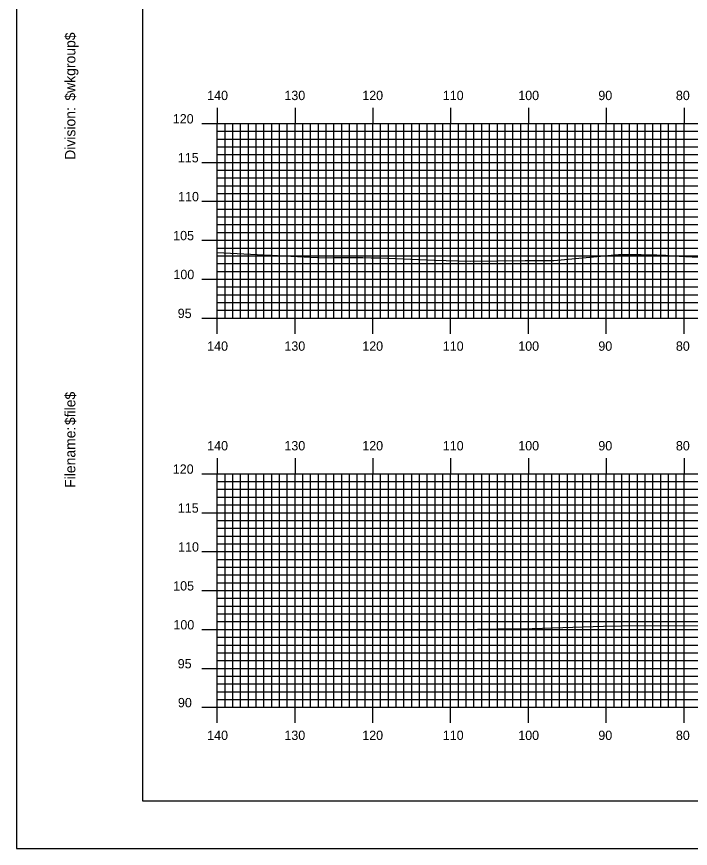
# Model space of a CAD drawing. Extents: x 1765726 to 1766069, y 442591 to 442811.
# Drawn here: x 1765726.1 to 1765812.7, y 442590.5 to 442697.4 of the extents above; entities that cross this region are included whole.
import ezdxf

# ---------------------------------------------------------------- set-up
doc = ezdxf.new("R2010")
doc.units = 0
for name, color, linetype in [('BORDER', 7, 'Continuous'), ('H_V ANNOTATION', 7, 'Continuous'), ('MAJOR', 7, 'Continuous'), ('MINOR', 7, 'Continuous'), ('PLOT BOUNDARY', 7, 'Continuous'), ('S_Roadway_Centerline', 7, 'Continuous')]:
    doc.layers.add(name, color=color, linetype=linetype)

msp = doc.modelspace()

# ---------------------------------------------------------------- linework, layer by layer
at = {"layer": 'BORDER'}
msp.add_lwpolyline([(1765742.28, 442596.67), (1766062.28, 442596.67), (1766062.28, 442806.67), (1765742.28, 442806.67)], close=True, dxfattribs=at)
at = {"layer": 'MAJOR'}
for p, q in [((1765751.88, 442685.67), (1765751.88, 442683.67)), ((1765761.88, 442685.67), (1765761.88, 442683.67)), ((1765771.88, 442685.67), (1765771.88, 442683.67)), ((1765781.88, 442685.67), (1765781.88, 442683.67)), ((1765791.88, 442685.67), (1765791.88, 442683.67)), ((1765801.88, 442685.67), (1765801.88, 442683.67)), ((1765811.88, 442685.67), (1765811.88, 442683.67)), ((1765749.88, 442683.67), (1765751.88, 442683.67)), ((1765751.88, 442683.67), (1766031.88, 442683.67)), ((1765751.88, 442658.67), (1765751.88, 442683.67)), ((1765751.88, 442658.67), (1765751.88, 442683.67)), ((1765751.88, 442683.67), (1766031.88, 442683.67)), ((1765761.88, 442658.67), (1765761.88, 442683.67)), ((1765771.88, 442658.67), (1765771.88, 442683.67)), ((1765781.88, 442658.67), (1765781.88, 442683.67)), ((1765791.88, 442658.67), (1765791.88, 442683.67)), ((1765801.88, 442658.67), (1765801.88, 442683.67)), ((1765811.88, 442658.67), (1765811.88, 442683.67)), ((1765749.88, 442678.67), (1765751.88, 442678.67)), ((1765751.88, 442678.67), (1766031.88, 442678.67)), ((1765749.88, 442673.67), (1765751.88, 442673.67)), ((1765751.88, 442673.67), (1766031.88, 442673.67)), ((1765749.88, 442668.67), (1765751.88, 442668.67)), ((1765751.88, 442668.67), (1766031.88, 442668.67)), ((1765749.88, 442663.67), (1765751.88, 442663.67)), ((1765751.88, 442663.67), (1766031.88, 442663.67)), ((1765749.88, 442658.67), (1765751.88, 442658.67)), ((1765751.88, 442658.67), (1766031.88, 442658.67)), ((1765751.88, 442658.67), (1766031.88, 442658.67)), ((1765751.88, 442656.66), (1765751.88, 442658.67)), ((1765761.88, 442656.66), (1765761.88, 442658.67)), ((1765771.88, 442656.66), (1765771.88, 442658.67)), ((1765781.88, 442656.66), (1765781.88, 442658.67)), ((1765791.88, 442656.66), (1765791.88, 442658.67)), ((1765801.88, 442656.66), (1765801.88, 442658.67)), ((1765811.88, 442656.66), (1765811.88, 442658.67)), ((1765751.88, 442640.67), (1765751.88, 442638.67)), ((1765761.88, 442640.67), (1765761.88, 442638.67)), ((1765771.88, 442640.67), (1765771.88, 442638.67)), ((1765781.88, 442640.67), (1765781.88, 442638.67)), ((1765791.88, 442640.67), (1765791.88, 442638.67)), ((1765801.88, 442640.67), (1765801.88, 442638.67)), ((1765811.88, 442640.67), (1765811.88, 442638.67)), ((1765749.88, 442638.67), (1765751.88, 442638.67)), ((1765751.88, 442638.67), (1766031.88, 442638.67)), ((1765751.88, 442608.67), (1765751.88, 442638.67)), ((1765751.88, 442608.67), (1765751.88, 442638.67)), ((1765751.88, 442638.67), (1766031.88, 442638.67)), ((1765761.88, 442608.67), (1765761.88, 442638.67)), ((1765771.88, 442608.67), (1765771.88, 442638.67)), ((1765781.88, 442608.67), (1765781.88, 442638.67)), ((1765791.88, 442608.67), (1765791.88, 442638.67)), ((1765801.88, 442608.67), (1765801.88, 442638.67)), ((1765811.88, 442608.67), (1765811.88, 442638.67)), ((1765749.88, 442633.67), (1765751.88, 442633.67)), ((1765751.88, 442633.67), (1766031.88, 442633.67)), ((1765749.88, 442628.67), (1765751.88, 442628.67)), ((1765751.88, 442628.67), (1766031.88, 442628.67)), ((1765749.88, 442623.67), (1765751.88, 442623.67)), ((1765751.88, 442623.67), (1766031.88, 442623.67)), ((1765749.88, 442618.67), (1765751.88, 442618.67)), ((1765751.88, 442618.67), (1766031.88, 442618.67)), ((1765749.88, 442613.67), (1765751.88, 442613.67)), ((1765751.88, 442613.67), (1766031.88, 442613.67)), ((1765749.88, 442608.67), (1765751.88, 442608.67)), ((1765751.88, 442608.67), (1766031.88, 442608.67)), ((1765751.88, 442608.67), (1766031.88, 442608.67)), ((1765751.88, 442606.66), (1765751.88, 442608.67)), ((1765761.88, 442606.66), (1765761.88, 442608.67)), ((1765771.88, 442606.66), (1765771.88, 442608.67)), ((1765781.88, 442606.66), (1765781.88, 442608.67)), ((1765791.88, 442606.66), (1765791.88, 442608.67)), ((1765801.88, 442606.66), (1765801.88, 442608.67)), ((1765811.88, 442606.66), (1765811.88, 442608.67))]:
    msp.add_line(p, q, dxfattribs=at)
at = {"layer": 'MINOR'}
for p, q in [((1765751.88, 442658.67), (1765751.88, 442683.67)), ((1765752.88, 442658.67), (1765752.88, 442683.67)), ((1765753.88, 442658.67), (1765753.88, 442683.67)), ((1765754.88, 442658.67), (1765754.88, 442683.67)), ((1765755.88, 442658.67), (1765755.88, 442683.67)), ((1765756.88, 442658.67), (1765756.88, 442683.67)), ((1765757.88, 442658.67), (1765757.88, 442683.67)), ((1765758.88, 442658.67), (1765758.88, 442683.67)), ((1765759.88, 442658.67), (1765759.88, 442683.67)), ((1765760.88, 442658.67), (1765760.88, 442683.67)), ((1765762.88, 442658.67), (1765762.88, 442683.67)), ((1765763.88, 442658.67), (1765763.88, 442683.67)), ((1765764.88, 442658.67), (1765764.88, 442683.67)), ((1765765.88, 442658.67), (1765765.88, 442683.67)), ((1765766.88, 442658.67), (1765766.88, 442683.67)), ((1765767.88, 442658.67), (1765767.88, 442683.67)), ((1765768.88, 442658.67), (1765768.88, 442683.67)), ((1765769.88, 442658.67), (1765769.88, 442683.67)), ((1765770.88, 442658.67), (1765770.88, 442683.67)), ((1765772.88, 442658.67), (1765772.88, 442683.67)), ((1765773.88, 442658.67), (1765773.88, 442683.67)), ((1765774.88, 442658.67), (1765774.88, 442683.67)), ((1765775.88, 442658.67), (1765775.88, 442683.67)), ((1765776.88, 442658.67), (1765776.88, 442683.67)), ((1765777.88, 442658.67), (1765777.88, 442683.67)), ((1765778.88, 442658.67), (1765778.88, 442683.67)), ((1765779.88, 442658.67), (1765779.88, 442683.67)), ((1765780.88, 442658.67), (1765780.88, 442683.67)), ((1765782.88, 442658.67), (1765782.88, 442683.67)), ((1765783.88, 442658.67), (1765783.88, 442683.67)), ((1765784.88, 442658.67), (1765784.88, 442683.67)), ((1765785.88, 442658.67), (1765785.88, 442683.67)), ((1765786.88, 442658.67), (1765786.88, 442683.67)), ((1765787.88, 442658.67), (1765787.88, 442683.67)), ((1765788.88, 442658.67), (1765788.88, 442683.67)), ((1765789.88, 442658.67), (1765789.88, 442683.67)), ((1765790.88, 442658.67), (1765790.88, 442683.67)), ((1765792.88, 442658.67), (1765792.88, 442683.67)), ((1765793.88, 442658.67), (1765793.88, 442683.67)), ((1765794.88, 442658.67), (1765794.88, 442683.67)), ((1765795.88, 442658.67), (1765795.88, 442683.67)), ((1765796.88, 442658.67), (1765796.88, 442683.67)), ((1765797.88, 442658.67), (1765797.88, 442683.67)), ((1765798.88, 442658.67), (1765798.88, 442683.67)), ((1765799.88, 442658.67), (1765799.88, 442683.67)), ((1765800.88, 442658.67), (1765800.88, 442683.67)), ((1765802.88, 442658.67), (1765802.88, 442683.67)), ((1765803.88, 442658.67), (1765803.88, 442683.67)), ((1765804.88, 442658.67), (1765804.88, 442683.67)), ((1765805.88, 442658.67), (1765805.88, 442683.67)), ((1765806.88, 442658.67), (1765806.88, 442683.67)), ((1765807.88, 442658.67), (1765807.88, 442683.67)), ((1765808.88, 442658.67), (1765808.88, 442683.67)), ((1765809.88, 442658.67), (1765809.88, 442683.67)), ((1765810.88, 442658.67), (1765810.88, 442683.67)), ((1765751.88, 442682.67), (1766031.88, 442682.67)), ((1765751.88, 442682.67), (1765753.89, 442682.67)), ((1765751.88, 442681.67), (1766031.88, 442681.67)), ((1765751.88, 442681.67), (1765753.89, 442681.67)), ((1765751.88, 442680.67), (1766031.88, 442680.67)), ((1765751.88, 442680.67), (1765753.89, 442680.67)), ((1765751.88, 442679.67), (1766031.88, 442679.67)), ((1765751.88, 442679.67), (1765753.89, 442679.67)), ((1765751.88, 442677.67), (1766031.88, 442677.67)), ((1765751.88, 442677.67), (1765753.89, 442677.67)), ((1765751.88, 442676.67), (1766031.88, 442676.67)), ((1765751.88, 442676.67), (1765753.89, 442676.67)), ((1765751.88, 442675.67), (1766031.88, 442675.67)), ((1765751.88, 442675.67), (1765753.89, 442675.67)), ((1765751.88, 442674.67), (1766031.88, 442674.67)), ((1765751.88, 442674.67), (1765753.89, 442674.67)), ((1765751.88, 442672.67), (1766031.88, 442672.67)), ((1765751.88, 442672.67), (1765753.89, 442672.67)), ((1765751.88, 442671.67), (1766031.88, 442671.67)), ((1765751.88, 442671.67), (1765753.89, 442671.67)), ((1765751.88, 442670.67), (1766031.88, 442670.67)), ((1765751.88, 442670.67), (1765753.89, 442670.67)), ((1765751.88, 442669.67), (1766031.88, 442669.67)), ((1765751.88, 442669.67), (1765753.89, 442669.67)), ((1765751.88, 442667.67), (1766031.88, 442667.67)), ((1765751.88, 442667.67), (1765753.89, 442667.67)), ((1765751.88, 442666.67), (1766031.88, 442666.67)), ((1765751.88, 442666.67), (1765753.89, 442666.67)), ((1765751.88, 442665.67), (1766031.88, 442665.67)), ((1765751.88, 442665.67), (1765753.89, 442665.67)), ((1765751.88, 442664.67), (1766031.88, 442664.67)), ((1765751.88, 442664.67), (1765753.89, 442664.67)), ((1765751.88, 442662.67), (1766031.88, 442662.67)), ((1765751.88, 442662.67), (1765753.89, 442662.67)), ((1765751.88, 442661.67), (1766031.88, 442661.67)), ((1765751.88, 442661.67), (1765753.89, 442661.67)), ((1765751.88, 442660.67), (1766031.88, 442660.67)), ((1765751.88, 442660.67), (1765753.89, 442660.67)), ((1765751.88, 442659.67), (1766031.88, 442659.67)), ((1765751.88, 442659.67), (1765753.89, 442659.67)), ((1765752.88, 442608.67), (1765752.88, 442638.67)), ((1765753.88, 442608.67), (1765753.88, 442638.67)), ((1765754.88, 442608.67), (1765754.88, 442638.67)), ((1765755.88, 442608.67), (1765755.88, 442638.67)), ((1765756.88, 442608.67), (1765756.88, 442638.67)), ((1765757.88, 442608.67), (1765757.88, 442638.67)), ((1765758.88, 442608.67), (1765758.88, 442638.67)), ((1765759.88, 442608.67), (1765759.88, 442638.67)), ((1765760.88, 442608.67), (1765760.88, 442638.67)), ((1765762.88, 442608.67), (1765762.88, 442638.67)), ((1765763.88, 442608.67), (1765763.88, 442638.67)), ((1765764.88, 442608.67), (1765764.88, 442638.67)), ((1765765.88, 442608.67), (1765765.88, 442638.67)), ((1765766.88, 442608.67), (1765766.88, 442638.67)), ((1765767.88, 442608.67), (1765767.88, 442638.67)), ((1765768.88, 442608.67), (1765768.88, 442638.67)), ((1765769.88, 442608.67), (1765769.88, 442638.67)), ((1765770.88, 442608.67), (1765770.88, 442638.67)), ((1765772.88, 442608.67), (1765772.88, 442638.67)), ((1765773.88, 442608.67), (1765773.88, 442638.67)), ((1765774.88, 442608.67), (1765774.88, 442638.67)), ((1765775.88, 442608.67), (1765775.88, 442638.67)), ((1765776.88, 442608.67), (1765776.88, 442638.67)), ((1765777.88, 442608.67), (1765777.88, 442638.67)), ((1765778.88, 442608.67), (1765778.88, 442638.67)), ((1765779.88, 442608.67), (1765779.88, 442638.67)), ((1765780.88, 442608.67), (1765780.88, 442638.67)), ((1765782.88, 442608.67), (1765782.88, 442638.67)), ((1765783.88, 442608.67), (1765783.88, 442638.67)), ((1765784.88, 442608.67), (1765784.88, 442638.67)), ((1765785.88, 442608.67), (1765785.88, 442638.67)), ((1765786.88, 442608.67), (1765786.88, 442638.67)), ((1765787.88, 442608.67), (1765787.88, 442638.67)), ((1765788.88, 442608.67), (1765788.88, 442638.67)), ((1765789.88, 442608.67), (1765789.88, 442638.67)), ((1765790.88, 442608.67), (1765790.88, 442638.67)), ((1765792.88, 442608.67), (1765792.88, 442638.67)), ((1765793.88, 442608.67), (1765793.88, 442638.67)), ((1765794.88, 442608.67), (1765794.88, 442638.67)), ((1765795.88, 442608.67), (1765795.88, 442638.67)), ((1765796.88, 442608.67), (1765796.88, 442638.67)), ((1765797.88, 442608.67), (1765797.88, 442638.67)), ((1765798.88, 442608.67), (1765798.88, 442638.67)), ((1765799.88, 442608.67), (1765799.88, 442638.67)), ((1765800.88, 442608.67), (1765800.88, 442638.67)), ((1765802.88, 442608.67), (1765802.88, 442638.67)), ((1765803.88, 442608.67), (1765803.88, 442638.67)), ((1765804.88, 442608.67), (1765804.88, 442638.67)), ((1765805.88, 442608.67), (1765805.88, 442638.67)), ((1765806.88, 442608.67), (1765806.88, 442638.67)), ((1765807.88, 442608.67), (1765807.88, 442638.67)), ((1765808.88, 442608.67), (1765808.88, 442638.67)), ((1765809.88, 442608.67), (1765809.88, 442638.67)), ((1765810.88, 442608.67), (1765810.88, 442638.67)), ((1765751.88, 442637.67), (1766031.88, 442637.67)), ((1765751.88, 442637.67), (1765753.89, 442637.67)), ((1765751.88, 442636.67), (1766031.88, 442636.67)), ((1765751.88, 442636.67), (1765753.89, 442636.67)), ((1765751.88, 442635.67), (1766031.88, 442635.67)), ((1765751.88, 442635.67), (1765753.89, 442635.67)), ((1765751.88, 442634.67), (1766031.88, 442634.67)), ((1765751.88, 442634.67), (1765753.89, 442634.67)), ((1765751.88, 442632.67), (1766031.88, 442632.67)), ((1765751.88, 442632.67), (1765753.89, 442632.67)), ((1765751.88, 442631.67), (1766031.88, 442631.67)), ((1765751.88, 442631.67), (1765753.89, 442631.67)), ((1765751.88, 442630.67), (1766031.88, 442630.67)), ((1765751.88, 442630.67), (1765753.89, 442630.67)), ((1765751.88, 442629.67), (1766031.88, 442629.67)), ((1765751.88, 442629.67), (1765753.89, 442629.67)), ((1765751.88, 442627.67), (1766031.88, 442627.67)), ((1765751.88, 442627.67), (1765753.89, 442627.67)), ((1765751.88, 442626.67), (1766031.88, 442626.67)), ((1765751.88, 442626.67), (1765753.89, 442626.67)), ((1765751.88, 442625.67), (1766031.88, 442625.67)), ((1765751.88, 442625.67), (1765753.89, 442625.67)), ((1765751.88, 442624.67), (1766031.88, 442624.67)), ((1765751.88, 442624.67), (1765753.89, 442624.67)), ((1765751.88, 442622.67), (1766031.88, 442622.67)), ((1765751.88, 442622.67), (1765753.89, 442622.67)), ((1765751.88, 442621.67), (1766031.88, 442621.67)), ((1765751.88, 442621.67), (1765753.89, 442621.67)), ((1765751.88, 442620.67), (1766031.88, 442620.67)), ((1765751.88, 442620.67), (1765753.89, 442620.67)), ((1765751.88, 442619.67), (1766031.88, 442619.67)), ((1765751.88, 442619.67), (1765753.89, 442619.67)), ((1765751.88, 442617.67), (1766031.88, 442617.67)), ((1765751.88, 442617.67), (1765753.89, 442617.67)), ((1765751.88, 442616.67), (1766031.88, 442616.67)), ((1765751.88, 442616.67), (1765753.89, 442616.67)), ((1765751.88, 442615.67), (1766031.88, 442615.67)), ((1765751.88, 442615.67), (1765753.89, 442615.67)), ((1765751.88, 442614.67), (1766031.88, 442614.67)), ((1765751.88, 442614.67), (1765753.89, 442614.67)), ((1765751.88, 442612.67), (1766031.88, 442612.67)), ((1765751.88, 442612.67), (1765753.89, 442612.67)), ((1765751.88, 442611.67), (1766031.88, 442611.67)), ((1765751.88, 442611.67), (1765753.89, 442611.67)), ((1765751.88, 442610.67), (1766031.88, 442610.67)), ((1765751.88, 442610.67), (1765753.89, 442610.67)), ((1765751.88, 442609.67), (1766031.88, 442609.67)), ((1765751.88, 442609.67), (1765753.89, 442609.67))]:
    msp.add_line(p, q, dxfattribs=at)
at = {"layer": 'PLOT BOUNDARY'}
msp.add_lwpolyline([(1765726.1, 442590.55), (1766066.1, 442590.55), (1766066.1, 442810.55), (1765726.1, 442810.55)], close=True, dxfattribs=at)
at = {"layer": 'S_Roadway_Centerline'}
for points in [[(1765751.88, 442667.08), (1765764.76, 442666.45), (1765765.92, 442666.41), (1765766.85, 442666.45), (1765767.84, 442666.44), (1765768.78, 442666.44), (1765769.65, 442666.44), (1765770.6, 442666.43), (1765771.65, 442666.42), (1765772.79, 442666.41), (1765779.74, 442666.12), (1765784.44, 442665.98), (1765791.47, 442666.08), (1765792.91, 442666.07), (1765794.26, 442666.06), (1765795.14, 442666.05), (1765803.47, 442666.84), (1765803.9, 442666.84), (1765804.36, 442666.83), (1765805.35, 442666.83), (1765805.87, 442666.82), (1765806.38, 442666.82), (1765806.9, 442666.81), (1765807.4, 442666.8), (1765807.89, 442666.79), (1765808.37, 442666.78), (1765808.91, 442666.76), (1765809.55, 442666.73), (1765810.33, 442666.68), (1765811.26, 442666.63), (1765813.72, 442666.48)], [(1765751.88, 442618.71), (1765755.42, 442618.66), (1765763.4, 442618.64), (1765767.92, 442618.62), (1765769.94, 442618.62), (1765779.99, 442618.63), (1765787.98, 442618.73), (1765792.36, 442618.78), (1765801.52, 442619.09), (1765806.02, 442619.18), (1765816.98, 442619.14)]]:
    msp.add_lwpolyline(points, dxfattribs=at)

# ---------------------------------------------------------------- texts
at = {"layer": 'BORDER'}
for s, p in [('$wkgroup$', (1765733.65, 442686.6)), ('Division:', (1765733.65, 442679)), ('$file$', (1765733.65, 442644.92)), ('Filename:', (1765733.65, 442636.86))]:
    msp.add_text(s, height=1.339, rotation=90, dxfattribs=at).set_placement(p)
at = {"layer": 'H_V ANNOTATION'}
for s, p in [('140', (1765750.59, 442686.67)), ('130', (1765760.51, 442686.67)), ('120', (1765770.52, 442686.67)), ('110', (1765780.87, 442686.67)), ('100', (1765790.57, 442686.67)), ('90', (1765800.86, 442686.67)), ('80', (1765810.83, 442686.67)), ('120', (1765746.17, 442683.67)), ('115', (1765746.82, 442678.67)), ('110', (1765746.85, 442673.67)), ('105', (1765746.22, 442668.67)), ('100', (1765746.25, 442663.67)), ('95', (1765746.8, 442658.67)), ('140', (1765750.59, 442654.47)), ('130', (1765760.51, 442654.47)), ('120', (1765770.52, 442654.47)), ('110', (1765780.87, 442654.47)), ('100', (1765790.57, 442654.47)), ('90', (1765800.86, 442654.47)), ('80', (1765810.83, 442654.47)), ('140', (1765750.59, 442641.67)), ('130', (1765760.51, 442641.67)), ('120', (1765770.52, 442641.67)), ('110', (1765780.87, 442641.67)), ('100', (1765790.57, 442641.67)), ('90', (1765800.86, 442641.67)), ('80', (1765810.83, 442641.67)), ('120', (1765746.17, 442638.67)), ('115', (1765746.82, 442633.67)), ('110', (1765746.85, 442628.67)), ('105', (1765746.22, 442623.67)), ('100', (1765746.25, 442618.67)), ('95', (1765746.8, 442613.67)), ('90', (1765746.83, 442608.67)), ('140', (1765750.59, 442604.47)), ('130', (1765760.51, 442604.47)), ('120', (1765770.52, 442604.47)), ('110', (1765780.87, 442604.47)), ('100', (1765790.57, 442604.47)), ('90', (1765800.86, 442604.47)), ('80', (1765810.83, 442604.47))]:
    msp.add_text(s, height=1.2, dxfattribs=at).set_placement(p)
at = {"layer": 'MAJOR'}
for p in [(1765751.88, 442658.67), (1765751.88, 442608.67)]:
    msp.add_text('-', height=0.012, dxfattribs=at).set_placement(p)

doc.saveas('drawing.dxf')
